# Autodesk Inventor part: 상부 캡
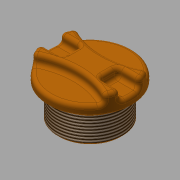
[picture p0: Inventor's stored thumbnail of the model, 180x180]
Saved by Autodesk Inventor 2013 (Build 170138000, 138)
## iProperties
Created: 2016-09
Part Number: 상부 캡
Material: ABS 플라스틱
Document SubType Name: Modeling
Designer: mduedu
Density: 1.493 g/cm^3
Author: mduedu
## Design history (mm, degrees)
sketch "스케치1"
  geometry: C1 r 22.5 at (0, 0); 1 further point
  constraints: 1 centre point, 1 coincident
  dimensions: "d0" = 45 diameter of C1
extrude "돌출1" new body sketch "스케치1" distance "d1" = 10; taper "d2" = 0 deg
sketch "스케치2" dims "d4" = 80
  geometry: C1 r 22.5 at (0, 0) reference; 3 further points
  constraints: 3 vertical alignment, 2 other
  dimensions: "d3" = 7 distance of point (0, 7) point (0, 0)
extrude "돌출2" cut sketch "스케치2" distance "d5" = 5; taper "d6" = 0 deg
sketch "스케치3"
  geometry: L1 (-22.5, 0)-(0, 0); L2 (-21.937, 5)-(-10, 5); L3 (-10, 5)-(-10, -5); L4 (-10, -5)-(-21.937, -5); A1 r 22.5 centre (0, 0) between (-19.118, 11.864) and (-19.118, -11.864) reference; A2 r 22.5 centre (0, 0) between (-21.937, 5) and (-21.937, -5); 1 further point
  constraints: 8 end point, 5 point on circle, 2 horizontal, 1 centre point, 1 coincident, 1 parallel, 1 perpendicular, 1 symmetric about line
  dimensions: "d7" = 10 distance from line of L3 point (0, 0); "d8" = 10 distance of L2.end L3.end
extrude "돌출3" cut sketch "스케치3" distance "d9" = 5; taper "d10" = 0 deg
fillet "모깎기1" dims "d11" = 2
fillet "모깎기2" dims "d12" = 2
fillet "모깎기3" dims "d13" = 2
sketch "스케치4"
  geometry: C1 r 17.5 at (0, 0); 1 further point
  constraints: 1 centre point, 1 coincident
  dimensions: "d14" = 35 diameter of C1
extrude "돌출4" join sketch "스케치4" distance "d15" = 17; taper "d16" = 0 deg
sketch "스케치5"
  geometry: C1 r 12.5 at (0, 0); 1 further point
  constraints: 1 centre point, 1 coincident
  dimensions: "d17" = 25 diameter of C1
extrude "돌출5" cut sketch "스케치5" distance "d18" = 10; taper "d19" = 0 deg
fillet "모깎기4" dims "d20" = 3
sketch "스케치6"
  geometry: L1 (7, 7)-(8, 7) reference; L2 (10, 5)-(10, -5) reference; L3 (8, -7)-(7, -7) reference; L4 (5, -9)-(5, -20.5) reference; L5 (3, -22.5)-(0, -22.5) reference; L6 (0, -22.5)-(0, -17.5) reference; L7 (0, -17.5)-(-17, -17.5) reference; L8 (-17, -17.5)-(-17, -12.5) reference; L9 (-17, -12.5)-(-10, -12.5) reference; L10 (-7, -9.5)-(-7, 9.5) reference; L11 (-10, 12.5)-(-17, 12.5) reference; L12 (-17, 12.5)-(-17, 17.5) reference; L13 (-17, 17.5)-(0, 17.5) reference; L14 (0, 17.5)-(0, 22.5) reference; L15 (0, 22.5)-(3, 22.5) reference; L16 (5, 20.5)-(5, 9) reference; L17 (0, -17.5)-(-2, -17.5); L18 (-2, -17.5)-(-2, -16.5); L19 (-2, -16.5)-(0, -16.5); L20 (0, -16.5)-(0, -17.5); L21 (0, 0)-(-7, 0); A1 r 2 centre (7, 9) between (5, 9) and (7, 7) reference; A2 r 2 centre (8, 5) between (10, 5) and (8, 7) reference; A3 r 2 centre (8, -5) between (8, -7) and (10, -5) reference; A4 r 2 centre (7, -9) between (7, -7) and (5, -9) reference; A5 r 2 centre (3, -20.5) between (3, -22.5) and (5, -20.5) reference; A6 r 3 centre (-10, -9.5) between (-10, -12.5) and (-7, -9.5) reference; A7 r 3 centre (-10, 9.5) between (-7, 9.5) and (-10, 12.5) reference; A8 r 2 centre (3, 20.5) between (5, 20.5) and (3, 22.5) reference
  constraints: 10 end point, 2 parallel, 1 horizontal, 1 midpoint, 1 perpendicular
  dimensions: "d26" = 2 distance of L6.end L17.end; "d27" = 1 distance of L17.end L18.end
revolve "회전1" sketch "스케치6" stored, may be unused: angle "d28" = 90 deg
feature "스레드1" dims "d21" = 10, "d22" = 0
chamfer "모따기1" distance "d23" = 1; stored, may be unused: second distance "d24" = 2, angle "d25" = 45 deg
sketch "스케치7"
  geometry: L1 (7, 7)-(8, 7) reference; L2 (10, 5)-(10, -5) reference; L3 (8, -7)-(7, -7) reference; L4 (5, -9)-(5, -20.5) reference; L5 (3, -22.5)-(0, -22.5) reference; L6 (0, -22.5)-(0, -16.5) reference; L7 (0, -16.5)-(-2, -16.5) reference; L8 (-2, -16.5)-(-3, -17.5) reference; L9 (-3, -17.5)-(-16, -17.5) reference; L10 (-16, -17.5)-(-17, -16.5) reference; L11 (-17, -16.5)-(-17, -12.5) reference; L12 (-17, -12.5)-(-10, -12.5) reference; L13 (-7, -9.5)-(-7, 9.5) reference; L14 (-10, 12.5)-(-17, 12.5) reference; L15 (-17, 12.5)-(-17, 16.5) reference; L16 (-17, 16.5)-(-16, 17.5) reference; L17 (-16, 17.5)-(-3, 17.5) reference; L18 (-3, 17.5)-(-2, 16.5) reference; L19 (-2, 16.5)-(0, 16.5) reference; L20 (0, 16.5)-(0, 22.5) reference; L21 (0, 22.5)-(3, 22.5) reference; L22 (5, 20.5)-(5, 9) reference; L23 (0, -22.5)-(1, -22.5); L24 (1, -22.5)-(1, -21.5); L25 (1, -21.5)-(0, -21.5); L26 (0, -21.5)-(0, -22.5); L27 (0, 0)-(-7, 0); A1 r 2 centre (7, 9) between (5, 9) and (7, 7) reference; A2 r 2 centre (8, 5) between (10, 5) and (8, 7) reference; A3 r 2 centre (8, -5) between (8, -7) and (10, -5) reference; A4 r 2 centre (7, -9) between (7, -7) and (5, -9) reference; A5 r 2 centre (3, -20.5) between (3, -22.5) and (5, -20.5) reference; A6 r 3 centre (-10, -9.5) between (-10, -12.5) and (-7, -9.5) reference; A7 r 3 centre (-10, 9.5) between (-7, 9.5) and (-10, 12.5) reference; A8 r 2 centre (3, 20.5) between (5, 20.5) and (3, 22.5) reference
  constraints: 10 end point, 2 parallel, 1 horizontal, 1 midpoint, 1 perpendicular
  dimensions: "d29" = 1 distance of L25.end L24.end; "d30" = 1 distance of L24.end L23.end
revolve "회전2" sketch "스케치7" stored, may be unused: angle "d31" = 90 deg
node "솔리드1"
mirror "대칭1"
mirror "대칭2"
node "투영된 루프1"
node "절단 모서리 투영1"
node "절단 모서리 투영2"
